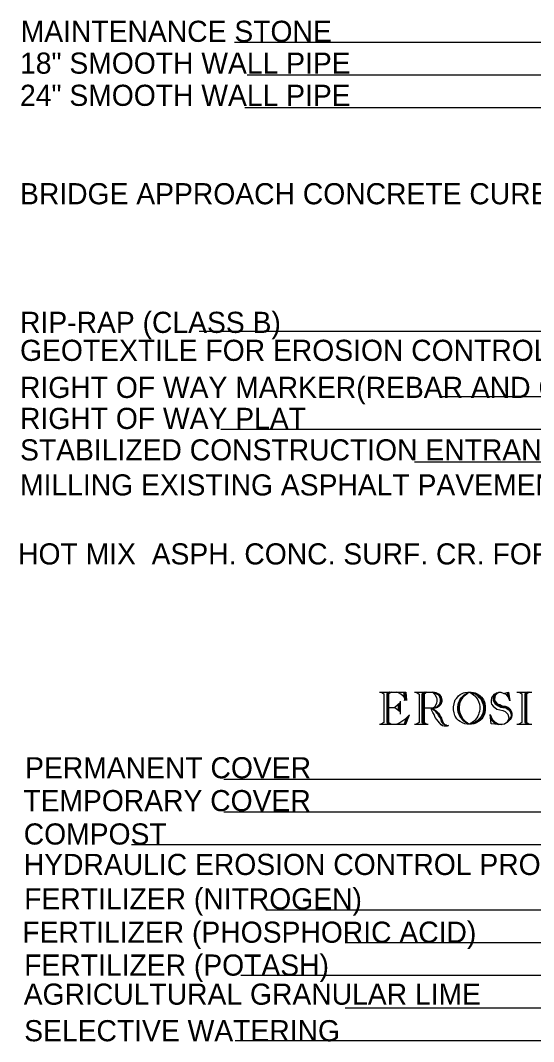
# Model space of a CAD drawing. Extents: x -13615 to 47191, y -1934 to 4415.
# Drawn here: x -11735.6 to -11541, y 1111.3 to 1498.5 of the extents above; entities that cross this region are included whole.
import ezdxf

# ---------------------------------------------------------------- set-up
doc = ezdxf.new("R2010")
doc.units = 0
doc.layers.add('Default', color=7, linetype='Continuous')

msp = doc.modelspace()

# ---------------------------------------------------------------- linework, layer by layer
at = {"layer": 'Default'}
for p, q in [((-11654.4, 1490.25), (-11428.18, 1490.25)), ((-11649.58, 1477.88), (-11428.19, 1477.88)), ((-11650.51, 1465.5), (-11428.21, 1465.5)), ((-11667.77, 1380.65), (-11428.31, 1380.65)), ((-11576.84, 1355.9), (-11428.35, 1355.9)), ((-11659.64, 1343.52), (-11428.37, 1343.52)), ((-11586.13, 1331.15), (-11428.38, 1331.15)), ((-11658.4, 1210.74), (-11394.23, 1210.74)), ((-11658.4, 1198.37), (-11394.28, 1198.37)), ((-11693.42, 1185.99), (-11394.32, 1185.99)), ((-11642.48, 1161.24), (-11394.4, 1161.24)), ((-11612.41, 1148.87), (-11394.44, 1148.87)), ((-11652.03, 1136.49), (-11394.48, 1136.49)), ((-11612.41, 1124.12), (-11394.53, 1124.12)), ((-11654.15, 1111.74), (-11394.57, 1111.74))]:
    msp.add_line(p, q, dxfattribs=at)
for points in [[(-11599.45, 1243.81), (-11589.51, 1243.81), (-11589.2, 1240.65), (-11589.67, 1241.28), (-11590.14, 1241.91), (-11590.62, 1242.39), (-11591.4, 1243.02), (-11592.19, 1243.49), (-11592.98, 1243.81)], [(-11598.98, 1243.81), (-11597.87, 1243.17), (-11597.87, 1232.29), (-11598.98, 1231.66)], [(-11595.67, 1243.81), (-11596.61, 1243.17), (-11596.61, 1232.29), (-11595.67, 1231.66)], [(-11595.35, 1243.81), (-11596.3, 1243.17), (-11596.3, 1232.29), (-11595.35, 1231.66)], [(-11594.88, 1243.81), (-11595.98, 1243.17), (-11595.98, 1232.29), (-11594.88, 1231.66)], [(-11590.3, 1243.81), (-11590.14, 1241.91)], [(-11589.98, 1243.81), (-11589.67, 1241.28)], [(-11586.2, 1243.81), (-11578.78, 1243.81), (-11578.15, 1243.65), (-11576.89, 1243.02), (-11576.1, 1241.91), (-11575.78, 1240.81), (-11575.78, 1240.18), (-11576.26, 1239.07), (-11576.73, 1238.6), (-11577.52, 1237.97), (-11578.62, 1237.65), (-11578.78, 1237.65), (-11577.68, 1237.97), (-11577.36, 1238.13), (-11576.73, 1238.91), (-11576.1, 1240.33), (-11576.1, 1241.12), (-11576.57, 1242.23), (-11576.89, 1242.7), (-11577.36, 1243.17), (-11578.15, 1243.49), (-11578.62, 1243.65), (-11579.41, 1243.81), (-11578.78, 1243.65), (-11578.31, 1243.49), (-11577.84, 1243.17), (-11577.36, 1242.86), (-11576.89, 1242.39), (-11576.57, 1241.6), (-11576.42, 1241.12), (-11576.42, 1240.33), (-11576.73, 1239.23), (-11577.84, 1238.13), (-11578.31, 1237.81), (-11578.78, 1237.65), (-11582.57, 1237.65)], [(-11585.57, 1243.81), (-11584.46, 1243.02), (-11584.46, 1232.29), (-11585.57, 1231.66)], [(-11582.25, 1243.81), (-11583.36, 1243.02), (-11583.36, 1232.29), (-11582.25, 1231.66)], [(-11581.94, 1243.81), (-11582.88, 1243.02), (-11582.88, 1232.29), (-11581.94, 1231.66)], [(-11581.46, 1243.81), (-11582.57, 1243.02), (-11582.57, 1232.29), (-11581.46, 1231.66)], [(-11579.41, 1243.81), (-11578.47, 1242.86), (-11577.84, 1241.75), (-11577.68, 1241.12), (-11577.68, 1240.33), (-11577.84, 1239.55), (-11578.47, 1238.28), (-11579.41, 1237.65), (-11578.78, 1237.18), (-11577.99, 1236.71), (-11577.05, 1235.76), (-11576.73, 1235.29), (-11576.57, 1234.97), (-11576.26, 1234.5), (-11575.94, 1233.87), (-11575.78, 1233.39), (-11575.63, 1232.76), (-11575.31, 1232.29), (-11575.15, 1231.97), (-11574.68, 1231.5), (-11574.21, 1231.34), (-11573.89, 1231.18), (-11573.26, 1231.18), (-11573.89, 1230.87), (-11574.99, 1230.87), (-11575.63, 1231.03), (-11576.1, 1231.34), (-11576.73, 1232.13), (-11577.68, 1233.39), (-11578.31, 1234.18), (-11578.78, 1235.29), (-11579.26, 1236.07), (-11579.57, 1236.86), (-11579.89, 1237.65)], [(-11568.84, 1232.6), (-11569.47, 1233.08), (-11570.1, 1233.71), (-11570.73, 1234.65), (-11570.89, 1234.97), (-11571.05, 1235.44), (-11571.21, 1235.92), (-11571.37, 1237.02), (-11571.37, 1238.28), (-11571.21, 1239.39), (-11571.05, 1240.02), (-11570.73, 1240.81), (-11570.26, 1241.44), (-11569.79, 1242.07), (-11569.47, 1242.39), (-11568.84, 1242.86), (-11568.37, 1243.17), (-11567.58, 1243.49), (-11567.11, 1243.65), (-11566, 1243.81), (-11565.37, 1243.81), (-11564.27, 1243.65), (-11563.79, 1243.49), (-11563, 1243.17), (-11562.53, 1242.86), (-11562.06, 1242.54), (-11561.27, 1241.75), (-11560.64, 1240.97), (-11560.32, 1240.49), (-11560.16, 1240.18), (-11560.01, 1239.7), (-11559.85, 1239.07), (-11559.69, 1238.13), (-11559.69, 1237.65), (-11559.85, 1236.39), (-11560.01, 1235.76), (-11560.16, 1235.44), (-11560.32, 1234.97), (-11560.64, 1234.5), (-11560.95, 1234.02), (-11561.58, 1233.39), (-11562.06, 1232.92), (-11562.53, 1232.6), (-11563.32, 1232.13), (-11563.79, 1231.97), (-11564.27, 1231.81), (-11565.37, 1231.66), (-11565.84, 1231.81), (-11566.16, 1231.97), (-11566.79, 1232.29), (-11567.42, 1232.76), (-11568.05, 1233.39), (-11568.68, 1234.18), (-11569, 1234.65), (-11569.31, 1235.29), (-11569.63, 1236.23), (-11569.79, 1237.34), (-11569.79, 1237.97), (-11569.63, 1239.07), (-11569.47, 1239.7), (-11569.31, 1240.18), (-11569.16, 1240.49), (-11569, 1240.81), (-11568.37, 1241.75), (-11567.74, 1242.39), (-11567.42, 1242.7), (-11566.95, 1243.02), (-11566.47, 1243.33), (-11566.16, 1243.49), (-11565.37, 1243.81), (-11564.11, 1243.49), (-11563.63, 1243.33), (-11563.32, 1243.17), (-11562.85, 1242.86), (-11562.37, 1242.54)], [(-11562.37, 1242.54), (-11561.9, 1242.07), (-11561.43, 1241.6), (-11561.11, 1241.28), (-11560.95, 1240.97), (-11560.48, 1240.02), (-11560.16, 1239.07), (-11560.01, 1238.13), (-11560.01, 1237.49), (-11560.16, 1236.39), (-11560.32, 1235.76), (-11560.64, 1234.97), (-11560.95, 1234.5), (-11561.27, 1234.02), (-11562.37, 1232.92), (-11563, 1232.45), (-11563.63, 1232.13), (-11564.11, 1231.97), (-11565.37, 1231.66), (-11566.32, 1232.13), (-11566.95, 1232.6), (-11567.74, 1233.23), (-11568.37, 1234.02), (-11568.84, 1234.97), (-11569.31, 1236.23), (-11569.47, 1237.34), (-11569.47, 1237.97), (-11569.31, 1239.23), (-11569.16, 1239.7), (-11568.84, 1240.49), (-11568.53, 1241.12), (-11568.21, 1241.6), (-11567.42, 1242.54), (-11566.79, 1243.02), (-11566.32, 1243.33), (-11565.37, 1243.81), (-11565.05, 1243.65), (-11564.27, 1243.17), (-11563.63, 1242.7), (-11563.32, 1242.39), (-11562.69, 1241.6), (-11562.21, 1240.81), (-11561.9, 1240.18), (-11561.58, 1239.23), (-11561.43, 1238.28), (-11561.43, 1237.49), (-11561.58, 1236.39), (-11561.74, 1235.76), (-11561.9, 1235.29), (-11562.21, 1234.65), (-11562.53, 1234.02), (-11563, 1233.39), (-11563.48, 1232.92), (-11564.27, 1232.29), (-11564.74, 1231.97), (-11565.37, 1231.66), (-11566.16, 1232.13), (-11566.63, 1232.45), (-11567.11, 1232.92), (-11567.74, 1233.55), (-11568.05, 1234.02), (-11568.53, 1234.97), (-11569, 1236.23), (-11569.16, 1237.34), (-11569.16, 1237.97), (-11569, 1239.23), (-11568.84, 1239.86), (-11568.53, 1240.65), (-11568.37, 1240.97), (-11568.05, 1241.44), (-11567.74, 1241.91), (-11567.26, 1242.39), (-11566.95, 1242.7), (-11566.16, 1243.33), (-11565.37, 1243.81), (-11564.74, 1243.81), (-11563.79, 1243.65), (-11563.16, 1243.49), (-11562.21, 1243.02), (-11561.43, 1242.54), (-11560.79, 1241.91), (-11560.32, 1241.28), (-11560.01, 1240.81), (-11559.69, 1240.02), (-11559.53, 1239.55), (-11559.37, 1238.28), (-11559.37, 1237.02), (-11559.53, 1235.92), (-11559.69, 1235.44), (-11559.85, 1234.97), (-11560.32, 1234.18), (-11560.64, 1233.71), (-11561.27, 1233.08), (-11561.9, 1232.6), (-11562.69, 1232.13), (-11563.63, 1231.81), (-11564.58, 1231.66), (-11566.16, 1231.66), (-11567.11, 1231.81), (-11568.05, 1232.13), (-11568.84, 1232.6)], [(-11552.43, 1243.33), (-11550.54, 1243.81), (-11550.06, 1240.49), (-11550.54, 1241.91), (-11550.7, 1242.07), (-11551.33, 1242.86), (-11552.43, 1243.33), (-11553.38, 1243.65), (-11554.32, 1243.65), (-11555.27, 1243.33), (-11556.06, 1242.86), (-11557.01, 1241.6), (-11557.16, 1240.65), (-11557.16, 1239.7), (-11557.01, 1239.23), (-11556.38, 1238.44), (-11554.96, 1237.34), (-11552.75, 1236.86), (-11551.8, 1236.39), (-11550.85, 1235.44), (-11550.38, 1234.02), (-11550.54, 1233.39), (-11551.17, 1232.29), (-11552.12, 1231.66), (-11552.9, 1231.5), (-11554.32, 1231.5), (-11557.16, 1231.81), (-11557.48, 1235.29), (-11556.69, 1233.55), (-11555.59, 1232.45), (-11554.48, 1231.81), (-11553.38, 1231.5), (-11554.32, 1231.66), (-11554.8, 1231.81), (-11555.43, 1232.13), (-11556.22, 1232.76), (-11556.85, 1233.55), (-11557.32, 1234.34)], [(-11554.17, 1243.65), (-11554.96, 1243.17), (-11555.59, 1242.54), (-11555.9, 1240.97), (-11555.74, 1240.49), (-11554.8, 1239.39), (-11553.85, 1239.07), (-11552.9, 1238.6), (-11551.8, 1238.44), (-11550.85, 1238.13), (-11550.06, 1237.49), (-11549.59, 1236.55), (-11549.28, 1235.76), (-11549.28, 1234.81), (-11549.59, 1233.87), (-11549.91, 1233.39), (-11550.54, 1232.76), (-11551.17, 1232.29), (-11550.38, 1233.08), (-11549.91, 1233.71), (-11549.43, 1234.65), (-11549.43, 1235.6), (-11549.59, 1236.39), (-11550.22, 1237.18), (-11551.33, 1238.13), (-11551.96, 1238.28), (-11552.9, 1238.28), (-11553.69, 1238.6), (-11554.32, 1238.76), (-11555.11, 1239.39), (-11555.59, 1240.02), (-11556.06, 1240.81), (-11556.06, 1241.6), (-11555.9, 1242.23), (-11555.43, 1243.02), (-11554.8, 1243.49), (-11555.59, 1243.02), (-11555.74, 1242.86), (-11556.06, 1242.39), (-11556.38, 1241.44), (-11556.38, 1240.65), (-11555.59, 1239.39), (-11554.48, 1238.6), (-11553.54, 1238.13), (-11552.75, 1237.97), (-11551.96, 1237.97), (-11551.01, 1237.49), (-11550.38, 1237.02), (-11549.91, 1236.39), (-11549.59, 1235.29), (-11549.59, 1234.65), (-11550.06, 1233.71), (-11551.17, 1232.29)], [(-11551.01, 1243.65), (-11550.7, 1242.07)], [(-11550.7, 1243.65), (-11550.38, 1241.6)], [(-11547.38, 1243.81), (-11541.7, 1243.81)], [(-11546.59, 1243.81), (-11545.49, 1243.17), (-11545.49, 1232.29), (-11546.59, 1231.66)], [(-11543.28, 1243.81), (-11544.38, 1243.17), (-11544.38, 1232.29), (-11543.28, 1231.66)], [(-11542.96, 1243.81), (-11544.07, 1243.17), (-11544.07, 1232.29), (-11542.96, 1231.66)], [(-11542.65, 1243.81), (-11543.75, 1243.17), (-11543.75, 1232.29), (-11542.65, 1231.66)], [(-11591.56, 1239.7), (-11593.61, 1237.97), (-11591.56, 1236.39)], [(-11591.88, 1239.39), (-11591.88, 1236.71)], [(-11591.56, 1240.33), (-11591.56, 1235.44)], [(-11589.98, 1240.65), (-11589.2, 1242.86)], [(-11595.98, 1237.97), (-11593.61, 1237.97)], [(-11592.35, 1239.07), (-11592.35, 1237.02)], [(-11579.57, 1237.65), (-11579.1, 1237.34), (-11578.62, 1237.02), (-11577.36, 1235.76), (-11576.89, 1235.13), (-11576.42, 1234.34), (-11576.1, 1233.71), (-11575.94, 1233.08), (-11575.63, 1232.29), (-11574.99, 1231.66), (-11574.05, 1231.18), (-11573.57, 1231.03), (-11574.21, 1231.18), (-11574.36, 1231.18), (-11575.15, 1231.66), (-11575.63, 1232.13), (-11575.94, 1232.6), (-11576.1, 1233.23), (-11576.26, 1233.55), (-11576.57, 1234.34), (-11577.05, 1234.97), (-11577.36, 1235.44), (-11577.68, 1235.76), (-11577.99, 1236.23), (-11578.47, 1236.71), (-11578.78, 1236.86), (-11579.1, 1237.18), (-11579.41, 1237.34), (-11579.73, 1237.65)], [(-11599.45, 1231.66), (-11589.51, 1231.66), (-11588.09, 1235.13), (-11589.35, 1233.87), (-11589.83, 1233.39), (-11591.72, 1232.13), (-11592.35, 1231.81), (-11592.82, 1231.66)], [(-11589.35, 1233.87), (-11590.14, 1231.66)], [(-11588.72, 1234.5), (-11589.83, 1231.66)], [(-11586.2, 1231.66), (-11580.99, 1231.66)], [(-11557.32, 1233.87), (-11556.69, 1232.92), (-11556.06, 1232.29), (-11555.43, 1231.97), (-11554.48, 1231.5)], [(-11547.38, 1231.66), (-11541.7, 1231.66)]]:
    msp.add_lwpolyline(points, dxfattribs=at)

# ---------------------------------------------------------------- texts
for s, height, p in [('MAINTENANCE STONE                                                                                                                                            50.000     ', 8.01562, (-11735.47, 1490.39)), ('18" SMOOTH WALL PIPE', 8.0156, (-11735.72, 1478.32)), ('24" SMOOTH WALL PIPE', 8.0156, (-11735.72, 1466.12)), ('BRIDGE APPROACH CONCRETE CURB AND GUTTER(1\'-10")', 8.0156, (-11735.72, 1428.8)), ('RIP-RAP (CLASS B)', 8.0156, (-11735.72, 1380.02)), ('GEOTEXTILE FOR EROSION CONTROL UNDER RIPRAP(CLASS 2)TYPE B', 8.0156, (-11735.72, 1369.41)), ('RIGHT OF WAY MARKER(REBAR AND CAP)', 8.0156, (-11735.72, 1355.36)), ('RIGHT OF WAY PLAT', 8.0156, (-11735.72, 1343.6)), ('STABILIZED CONSTRUCTION ENTRANCE', 8.0156, (-11735.72, 1331.66)), ('MILLING EXISTING ASPHALT PAVEMENT ( VARIABLE )', 8.0156, (-11735.72, 1318.37)), ('HOT MIX  ASPH. CONC. SURF. CR. FOR DITCH PAVING                                                                                     5.000             TON', 8.01562, (-11736.45, 1292.21)), ('PERMANENT COVER', 8.0156, (-11733.79, 1211.11)), ('TEMPORARY COVER', 8.0156, (-11734.49, 1198.64)), ('COMPOST', 8.016, (-11734.32, 1185.99)), ('HYDRAULIC EROSION CONTROL PRODUCT ( HECP)-TYPE 2', 8.0156, (-11734.31, 1174.45)), ('FERTILIZER (NITROGEN)', 8.0156, (-11734.14, 1161.4)), ('FERTILIZER (PHOSPHORIC ACID)', 8.0156, (-11734.85, 1148.75)), ('FERTILIZER (POTASH)', 8.0156, (-11734.14, 1136.28)), ('AGRICULTURAL GRANULAR LIME', 8.0156, (-11734.32, 1125.25)), ('SELECTIVE WATERING', 8.0156, (-11734.14, 1111.39))]:
    msp.add_text(s, height=height, dxfattribs=at).set_placement(p)

doc.saveas('drawing.dxf')
